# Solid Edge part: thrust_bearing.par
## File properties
Title: Thrust bearing
Author: vicky raina
Template: Normal.par
Last saved by: Robert a Rhodes jr
Revision: 8
Application: Solid Edge
Material: aluminum
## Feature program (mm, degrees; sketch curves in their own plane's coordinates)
sketch for "unnamed RevolvedProtrusion 1" plane through (0, 0, 0) normal (0, -1, 0) x-axis (1, 0, 0)
  line (47.625, 16.8036) -> (66.929, 16.8036)
  line (66.929, 16.8036) -> (73.025, 10.7076)
  line (73.025, 10.7076) -> (73.025, -12.0254)
  line (73.025, -12.0254) -> (66.929, -18.1214)
  line (66.929, -18.1214) -> (47.625, -18.1214)
  line (47.625, -18.1214) -> (47.625, -7.1994)
  line (61.5714, -7.1994) -> (47.625, -7.1994)
  line (61.5714, 5.8816) -> (61.5714, -7.1994)
  line (47.625, 5.8816) -> (61.5714, 5.8816)
  line (47.625, 5.8816) -> (47.625, 16.8036)
revolve "unnamed RevolvedProtrusion 1" add finite 360 deg
sketch for "unnamed RevolvedProtrusion 2" plane through (0, 0, 0) normal (1, 0, 0) x-axis (0, 1, 0)
  line (69.977, 13.7556) -> (73.0652, 13.7556)
  line (73.0652, 13.7556) -> (74.6125, 12.2083)
  line (74.6125, 12.2083) -> (74.6125, -13.4669)
  line (74.6125, -13.4669) -> (73.006, -15.0734)
  line (73.006, -15.0734) -> (69.977, -15.0734)
revolve "unnamed RevolvedProtrusion 2" add full turn 360 deg
sketch for "unnamed RevolvedProtrusion 3" plane through (0, 0, 0) normal (0, -1, 0) x-axis (1, 0, 0)
revolve "unnamed RevolvedProtrusion 3" add full turn 360 deg about sketch line (-54.9674, 10.1232) -> (-54.9674, -18.1214)
pattern "unnamed Pattern 1" of "unnamed RevolvedProtrusion 3"
pattern "unnamed Pattern 2"
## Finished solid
Body 1: solid body, 39 faces, 39 edges, 25 vertices.
  Faces by surface: torus 25, plane 6, cone 4, cylinder 4
  Edges by curve: circle 39
Bounding box of the edges (mm; curved faces can reach further): 149.225 x 149.225 x 34.925, from (-74.6125, -74.6125, -18.1214) to (74.6125, 74.6125, 16.8036).
Cylindrical faces by radius (mm): R47.625 x2, R61.5714 x1, R74.6125 x1
Conical faces (half-angle, radius in mm at the cone's reference point): 45 deg R66.929 x1, 45 deg R73.025 x1, 45 deg R73.0652 x1, 45 deg R74.6125 x1
Toroidal faces (ring radius, tube radius in mm): R-0.1023 r6.604 x25
Planar faces by outward normal: +z 3, -z 3
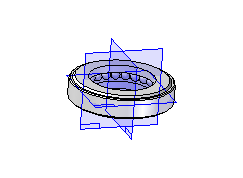
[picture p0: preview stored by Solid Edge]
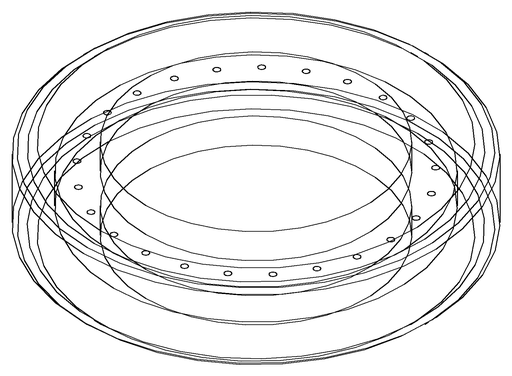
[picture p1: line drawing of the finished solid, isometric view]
